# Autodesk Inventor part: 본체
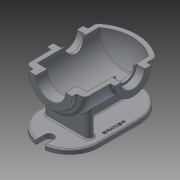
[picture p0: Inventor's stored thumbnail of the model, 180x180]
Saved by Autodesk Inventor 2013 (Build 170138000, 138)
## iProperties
Created: 2016-02
Part Number: 본체
Material: 알루미늄 6061
Document SubType Name: Modeling
Designer: mduedu
Density: 2.71 g/cm^3
Mass: 2164.61 g
Surface Area: 1516.76 cm^2
Volume: 798.749 cm^3
Author: mduedu
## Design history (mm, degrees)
sketch "스케치2"
  geometry: L1 (0, 90)-(0, -90); L2 (65, -65.993)-(65, 90); L3 (65, 90)-(0, 90); A1 r 100 centre (0, 10) between (0, -90) and (65, -65.993); 2 further points
  constraints: 6 end point, 2 point on circle, 1 centre point, 1 coincident, 1 horizontal, 1 midpoint, 1 parallel, 1 point on line, 1 vertical
  dimensions: "d3" = 180 distance of L1.start L1.end; "d5" = 130 diameter of L2 L1; "d6" = 100 radius of A1
revolve "회전1" sketch "스케치2" stored, may be unused: angle "d7" = 90 deg
sketch "스케치3"
  geometry: C1 r 47.5 at (0, 0); 1 further point
  constraints: 1 centre point, 1 coincident
  dimensions: "d8" = 95 diameter of C1
extrude "돌출2" join sketch "스케치3" distance "d10" = 10; taper "d11" = 0 deg
sketch "스케치5"
  geometry: L1 (47.5, 100)-(47.5, 90) reference; L2 (47.5, 90)-(65, 90) reference; L3 (65, 90)-(65, -65.993) reference; L4 (-65, -65.993)-(-65, 90) reference; L5 (-65, 90)-(-47.5, 90) reference; L6 (-47.5, 90)-(-47.5, 100) reference; L7 (-47.5, 100)-(47.5, 100) reference; L8 (55, 75)-(55, -61.239); L9 (0, 75)-(55, 75); L10 (0, 75)-(0, -80); A1 r 100 centre (0, 10) between (-65, -65.993) and (0, -90) reference; A2 r 100 centre (0, 10) between (0, -90) and (65, -65.993) reference; A3 r 90 centre (0, 10) between (0, -80) and (55, -61.239); 1 further point
  constraints: 6 end point, 2 point on circle, 1 centre point, 1 parallel, 1 perpendicular, 1 point on line, 1 vertical
  dimensions: "d13" = 10 distance between parallel lines of L3 L8; "d14" = 10 radial gap between concentric circles of A3 A1; "d15" = 15 distance between parallel lines of L9 L2
revolve "회전2" sketch "스케치5" stored, may be unused: angle "d16" = 90 deg
hole "구멍1" diameter "d19" = 65; stored, may be unused: countersink angle "d23" = 90 deg, drill point angle "d25" = 118 deg; dims "d17" = 10, "d18" = 10, "d20" = 6, "d21" = 4, "d22" = 2, "d24" = 8
node "작업 평면1"
sketch "스케치6"
  geometry: L1 (47.5, 100)-(-47.5, 100) reference; C1 r 40 at (0, -7); 1 further point
  constraints: 1 centre point, 1 vertical alignment
  dimensions: "d27" = 80 diameter of C1; "d29" = 107 distance from line of C1.centre L1
extrude "돌출3" join sketch "스케치6" stored distance "d30" = 10; taper "d31" = 0 deg
hole "구멍2" diameter "d34" = 42; stored, may be unused: countersink angle "d38" = 90 deg, drill point angle "d40" = 118 deg; dims "d32" = 10, "d33" = 10, "d35" = 6, "d36" = 52, "d37" = 18, "d39" = 8
sketch "스케치7" dims "d41" = 65
  geometry: C1 r 40 at (0, 0) reference; 3 further points
  constraints: 2 vertical alignment, 1 coincident, 2 other
hole "구멍3" sketch "스케치7" at (0, 32.5) diameter "d43" = 3.242; stored, may be unused: countersink angle "d47" = 90 deg, drill point angle "d49" = 118 deg; dims "d44" = 11, "d45" = 13, "d46" = 18, "d48" = 13
sketch "스케치8" dims "d53" = 80
  geometry: 3 further points
  constraints: 2 vertical alignment, 1 coincident, 2 other
hole "구멍4" sketch "스케치8" at (0, -40) diameter "d56" = 3.242; stored, may be unused: countersink angle "d60" = 90 deg, drill point angle "d62" = 118 deg; dims "d57" = 11, "d58" = 13, "d59" = 18, "d61" = 13
fillet "모깎기1" dims "d66" = 10
fillet "모깎기2" dims "d67" = 3
fillet "모깎기3" dims "d68" = 0.3
chamfer "모따기1" distance "d69" = 1; stored, may be unused: second distance "d70" = 2, angle "d71" = 45 deg
node "작업 평면5"
sketch "스케치10"
  geometry: L1 (-50, 66)-(50, 66); L2 (50, 66)-(50, 50); L3 (50, 50)-(-50, 50); L4 (-50, 50)-(-50, 66); 2 further points
  constraints: 8 end point, 2 horizontal, 2 vertical, 1 midpoint, 1 vertical alignment
  dimensions: "d177" = 50 distance from line of L3 point (0, 0); "d178" = 100 distance of L1.start L1.end; "d179" = 16 distance of L3.end L1.start
extrude "돌출5" join sketch "스케치10" stored distance "d84" = 10; taper "d85" = 0 deg
sketch "스케치21" dims "d180" = 220, "d182" = 130
  geometry: L1 (65, 58)-(-65, 58); L2 (-65, 58)-(-65, -32); L3 (-65, -32)-(65, -32); L4 (65, -32)-(65, 58); L5 (50, 50)-(50, 66) reference; 4 further points
  constraints: 8 end point, 3 horizontal alignment, 3 midpoint, 2 parallel, 1 horizontal, 1 perpendicular, 1 vertical alignment, 4 other
extrude "돌출13" join sketch "스케치21" distance "d183" = 10; taper "d184" = 0 deg
sketch "스케치11"
  geometry: L1 (-65, 80)-(-65, -61.239) reference; L2 (-100, -97)-(-100, -32) reference; L3 (-65, -42.793)-(-100, -63); L4 (-100, -97)-(-110, -97) reference; 1 further point
  constraints: 2 end point, 2 point on line
  dimensions: "d185" = 34 distance from line of L3.end L4; "d186" = 120 deg angle of L2 L3
feature "리브1" sketch "스케치11" dims "d88" = 1, "d89" = 16, "d90" = 0, "d91" = 0, "d92" = 1, "d93" = 1
fillet "모깎기12"
fillet "모깎기13"
fillet "모깎기16" dims "d167" = 3
fillet "모깎기18"
fillet "모깎기17" dims "d168" = 3
fillet "모깎기19" dims "d187" = 3
node "작업 평면6"
sketch "스케치19"
  geometry: L1 (75, -47)-(75, 33) reference; L2 (-75, -47)-(-75, 33) reference; L3 (75, -7)-(-75, -7); C1 r 22.5 at (0, -7); 1 further point
  constraints: 3 midpoint, 2 end point, 1 centre point
  dimensions: "d149" = 45 diameter of C1
extrude "돌출11" join sketch "스케치19" stored distance "d150" = 10; taper "d151" = 0 deg
hole "구멍6" diameter "d154" = 33.376; stored, may be unused: countersink angle "d158" = 90 deg, drill point angle "d160" = 118 deg; dims "d155" = 6, "d156" = 4, "d157" = 2, "d159" = 8, "d190" = 10, "d191" = 10
fillet "모깎기11" dims "d161" = 3
chamfer "모따기3" distance "d164" = 1; stored, may be unused: second distance "d165" = 2, angle "d166" = 45 deg
node "작업 평면9"
  node "작업 평면8"
sketch "스케치22" dims "d189" = 20
  geometry: L1 (-10, -123)-(10, -123); L2 (10, -123)-(10, -103); L3 (10, -103)-(-10, -103); L4 (-10, -103)-(-10, -123); A1 r 65 centre (0, -58) between (-65, -58) and (65, -58) reference; 2 further points
  constraints: 8 end point, 2 parallel, 1 horizontal, 1 horizontal alignment, 1 midpoint, 1 perpendicular, 1 tangent, 1 vertical alignment, 2 other
  dimensions: "d193" = 30 dimension on L1
extrude "돌출14" cut sketch "스케치22" stored distance "d194" = 10; taper "d195" = 0 deg
fillet "모깎기21" dims "d196" = 3
feature "분할1"
sketch "스케치23"
  geometry: L1 (-65, 32)-(-65, -58) reference; L2 (65, -58)-(65, 32) reference; L3 (-65, -13)-(65, -13); 2 further points
  constraints: 2 end point, 2 midpoint, 1 point on line, 1 other
  dimensions: "d197" = 12 distance from line of point (53, -13) L2
feature "엠보싱2" sketch "스케치23" dims "d8" = 95, "d198" = 0.5, "d199" = 0
node "솔리드2"
pattern_circular "원형 패턴1" dims angle "d51" = 360 deg
mirror "대칭1"
pattern_circular "원형 패턴2" dims angle "d64" = 360 deg
mirror "대칭3"
node "절단 모서리 투영1"
other parameters: "d26" = 75, "d136" = 175
